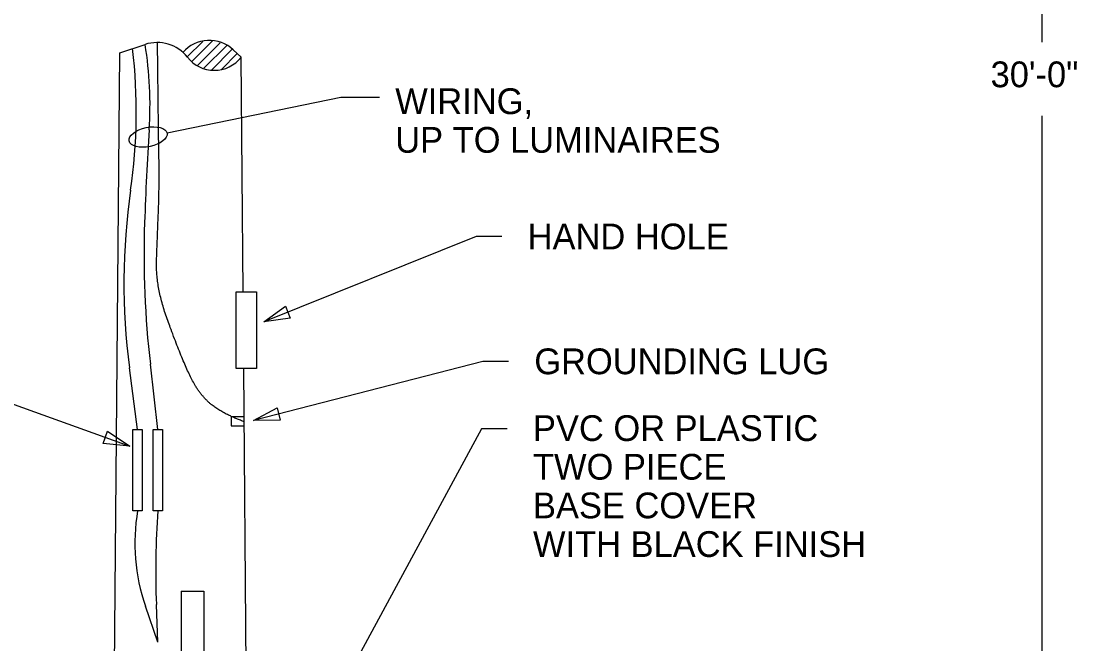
# Model space of a CAD drawing. Extents: x 10117 to 10169, y 10050 to 10161.
# Drawn here: x 10139.75 to 10167.06, y 10097.81 to 10113.92 of the extents above; entities that cross this region are included whole.
import ezdxf

# ---------------------------------------------------------------- set-up
doc = ezdxf.new("R2010")
doc.units = 0
for name, color, linetype in [('G-ANNO-TEXT', 7, 'Continuous'), ('G-DETL-LINE', 7, 'Continuous'), ('G-DETL-OTLN', 7, 'Continuous'), ('G-DETL-PATT', 7, 'Continuous')]:
    doc.layers.add(name, color=color, linetype=linetype)

msp = doc.modelspace()

# ---------------------------------------------------------------- linework, layer by layer
at = {"layer": 'G-ANNO-TEXT'}
for p, q in [((10166.163, 10113.381), (10166.163, 10132.951)), ((10166.163, 10092.896), (10166.163, 10111.47)), ((10151.52, 10108.351), (10146.028, 10106.144)), ((10152.186, 10108.351), (10151.52, 10108.351)), ((10136.385, 10105.139), (10142.558, 10102.93)), ((10151.692, 10105.121), (10145.764, 10103.594)), ((10152.359, 10105.121), (10151.692, 10105.121)), ((10151.658, 10103.375), (10146.864, 10094.509)), ((10152.325, 10103.375), (10151.658, 10103.375))]:
    msp.add_line(p, q, dxfattribs=at)
msp.add_lwpolyline([(10149.016, 10111.948), (10148.016, 10111.948), (10143.523, 10111.025)], dxfattribs=at)
for points in [[(10146.709, 10106.238), (10146.028, 10106.144), (10146.584, 10106.547)], [(10146.451, 10103.599), (10145.764, 10103.594), (10146.368, 10103.922)], [(10141.986, 10103.311), (10142.558, 10102.93), (10141.874, 10102.997)]]:
    msp.add_lwpolyline(points, close=True, dxfattribs=at)
msp.add_ellipse((10143.033, 10110.924), major_axis=(-0.49, -0.101), ratio=0.5, dxfattribs=at)
at = {"layer": 'G-DETL-LINE'}
for p, q in [((10142.641, 10103.361), (10142.883, 10103.361)), ((10142.641, 10101.257), (10142.641, 10103.361)), ((10142.883, 10103.361), (10142.883, 10101.257)), ((10143.166, 10101.257), (10143.166, 10103.361)), ((10143.166, 10103.361), (10143.409, 10103.361)), ((10143.409, 10103.361), (10143.409, 10101.257)), ((10142.883, 10101.257), (10142.641, 10101.257)), ((10143.409, 10101.257), (10143.166, 10101.257))]:
    msp.add_line(p, q, dxfattribs=at)
for points in [[(10142.762, 10103.361), (10142.551, 10104.955)], [(10143.288, 10103.361), (10143.092, 10105.045)], [(10143.288, 10097.859), (10142.964, 10098.789)], [(10143.288, 10097.859), (10143.247, 10098.83)]]:
    msp.add_lwpolyline(points, dxfattribs=at)
for centre, radius, start, end in [((10128.657, 10111.58), 14.071, 351.7125, 6.6561), ((10133.29, 10111.758), 9.792, 356.2289, 9.1747), ((10218.627, 10106.134), 75.729, 176.22885, 178.04968), ((10159.102, 10107.146), 16.695, 171.7125, 187.5389), ((10167.414, 10107.877), 24.487, 178.0497, 186.6413), ((10147.64, 10100.415), 4.95, 170.1985, 199.1669), ((10164.075, 10099.697), 20.846, 175.7073, 182.3843)]:
    msp.add_arc(centre, radius, start, end, dxfattribs=at)
msp.add_open_spline([(10145.503, 10103.566), (10144.953, 10103.766), (10144.327, 10104.292), (10143.852, 10105.318), (10143.226, 10107.046), (10143.276, 10108.397), (10143.326, 10109.674), (10143.301, 10111.126), (10143.276, 10113.379)], degree=2, dxfattribs=at)
at = {"layer": 'G-DETL-OTLN'}
for p, q in [((10142.13, 10093.045), (10142.301, 10113.1)), ((10145.491, 10106.922), (10145.439, 10112.99)), ((10145.309, 10106.922), (10145.835, 10106.922)), ((10145.309, 10104.939), (10145.309, 10106.922)), ((10145.835, 10106.922), (10145.835, 10104.939)), ((10145.835, 10104.939), (10145.309, 10104.939)), ((10145.609, 10093.045), (10145.508, 10104.939)), ((10143.885, 10099.179), (10144.477, 10099.179)), ((10143.885, 10099.179), (10143.885, 10086.825)), ((10144.477, 10099.179), (10144.477, 10086.825))]:
    msp.add_line(p, q, dxfattribs=at)
for points in [[(10142.301, 10113.1), (10142.954, 10113.319)], [(10145.439, 10112.99), (10145.237, 10113.178)]]:
    msp.add_lwpolyline(points, dxfattribs=at)
msp.add_lwpolyline([(10145.516, 10103.685), (10145.185, 10103.685), (10145.185, 10103.451), (10145.516, 10103.451)], close=True, dxfattribs=at)
for centre, radius, start, end in [((10144.616, 10112.512), 0.911, 46.9962, 138.5136), ((10143.27, 10112.377), 0.993, 38.0577, 108.5231), ((10144.745, 10113.532), 0.881, 218.0577, 321.992)]:
    msp.add_arc(centre, radius, start, end, dxfattribs=at)
at = {"layer": 'G-DETL-PATT'}
for p, q in [((10144.046, 10113), (10144.446, 10113.4)), ((10144.167, 10112.878), (10144.699, 10113.41)), ((10144.308, 10112.778), (10144.895, 10113.365)), ((10144.477, 10112.705), (10145.07, 10113.297)), ((10144.671, 10112.657), (10145.21, 10113.196)), ((10144.929, 10112.673), (10145.34, 10113.084))]:
    msp.add_line(p, q, dxfattribs=at)

# ---------------------------------------------------------------- texts
at = {"layer": 'G-ANNO-TEXT'}
for s, height, p in [('30\'-0"', 0.6667, (10164.831, 10112.213)), ('WIRING,', 0.6667, (10149.427, 10111.518)), ('UP TO LUMINAIRES', 0.66667, (10149.427, 10110.518)), ('HAND HOLE', 0.6667, (10152.853, 10108.018)), ('GROUNDING LUG', 0.66667, (10153.025, 10104.788)), ('PVC OR PLASTIC', 0.66667, (10152.991, 10103.06)), ('TWO PIECE', 0.6667, (10152.991, 10102.06)), ('BASE COVER', 0.6667, (10152.991, 10101.06)), ('WITH BLACK FINISH', 0.66667, (10152.991, 10100.06))]:
    msp.add_text(s, height=height, dxfattribs=at).set_placement(p)

doc.saveas('drawing.dxf')
